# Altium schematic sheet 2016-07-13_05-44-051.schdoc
size 331 x 127 mm; SheetNumber: 1; SheetTotal: 1
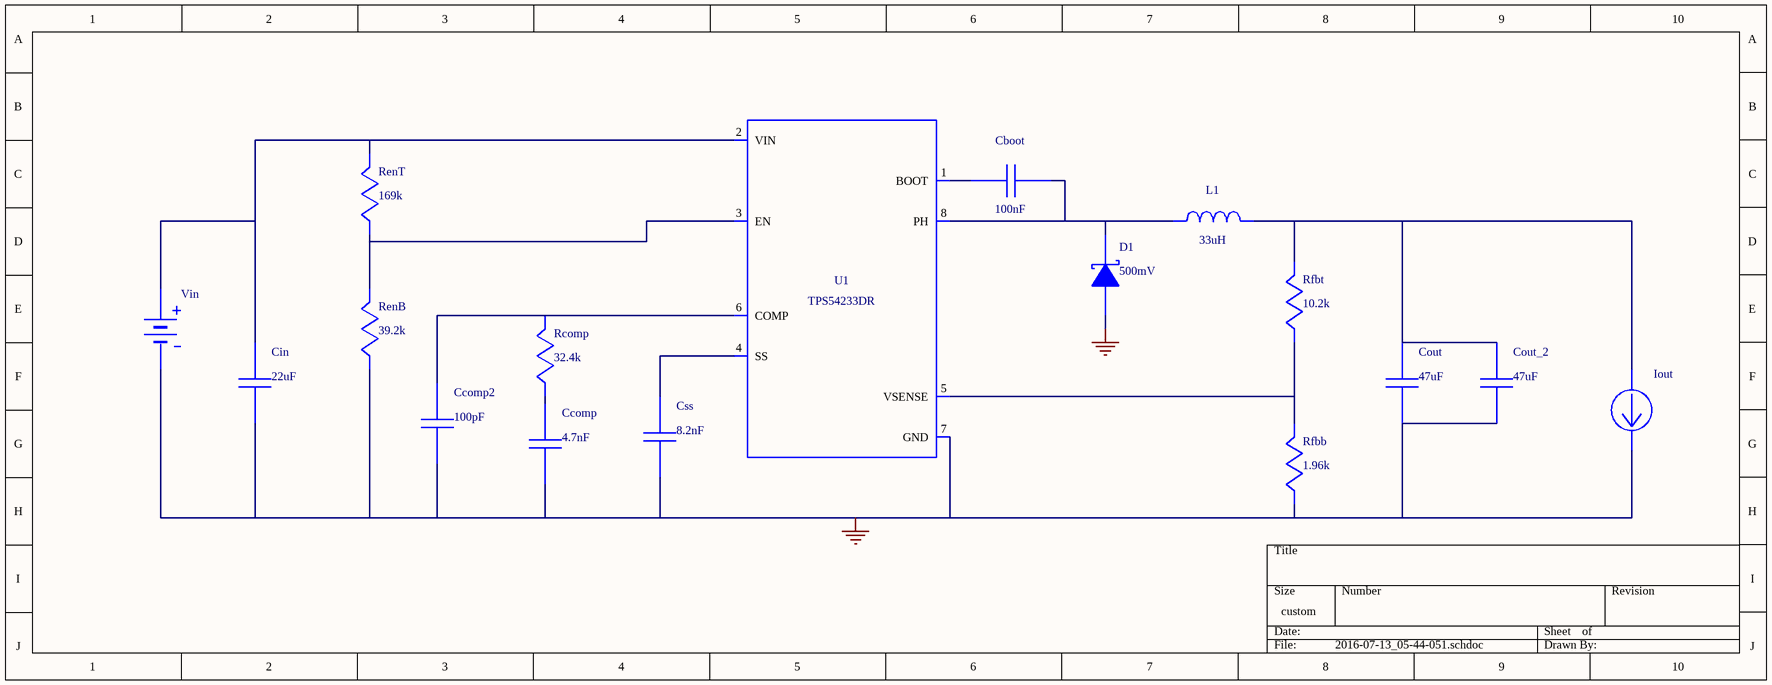
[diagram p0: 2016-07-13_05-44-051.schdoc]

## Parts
Cboot  value 100nF  (hidden comment: GRM155R61A104KA01D)
Ccomp  value 4.7nF  (hidden comment: CC0805KRX7R9BB472)
Ccomp2  value 100pF  (hidden comment: CC0805JRNPO9BN101)
Cin  value 22uF  (hidden comment: GRM32ER61E226KE15L)
Cout  value 47uF  (hidden comment: GRM31CR61A476KE15L)
Cout_2  value 47uF  (hidden comment: GRM31CR61A476KE15L)
Css  value 8.2nF  (hidden comment: GRM033R61A822KA01D)
D1  value 500mV  (hidden comment: B220-13-F)
Iout  WB_CURRENT_LOAD  (value not drawn)
L1  value 33uH  (hidden comment: SDR1105-330KL)
Rcomp  value 32.4k  (hidden comment: CRCW040232K4FKED)
RenB  value 39.2k  (hidden comment: CRCW040239K2FKED)
RenT  value 169k  (hidden comment: CRCW0402169KFKED)
Rfbb  value 1.96k  (hidden comment: CRCW04021K96FKED)
Rfbt  value 10.2k  (hidden comment: CRCW040210K2FKED)
U1  TPS54231DR  (value not drawn)
Vin  WB_BATTERY  (value not drawn)

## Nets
0: Ccomp.2 Ccomp2.2 Cin.2 Cout.2 Cout_2.2 Css.2 D1.2(A) Iout.2(-) RenB.2 Rfbb.2 U1.7(GND) Vin.2(-)
NetCboot_1: Cboot.1 U1.1(BOOT)
NetCboot_2: Cboot.2 D1.1(K) L1.2 U1.8(PH)
NetCcomp2_1: Ccomp2.1 Rcomp.1 U1.6(COMP)
NetCcomp_1: Ccomp.1 Rcomp.2
NetCin_1: Cin.1 RenT.1 U1.2(VIN) Vin.1(+)
NetCout_1: Cout.1 Cout_2.1 Iout.1(+) L1.1 Rfbt.1
NetCss_1: Css.1 U1.4(SS)
NetRenB_1: RenB.1 RenT.2 U1.3(EN)
NetRfbb_1: Rfbb.1 Rfbt.2 U1.5(VSENSE)

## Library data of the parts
Cboot = GRM155R61A104KA01D: GRM155R61A104KA0; Manufacturer Name: MuRata
Ccomp = CC0805KRX7R9BB472: CC0805KRX7R9BB47; Manufacturer Name: Yageo America
Ccomp2 = CC0805JRNPO9BN101: CC0805JRNPO9BN10; Manufacturer Name: Yageo America
Cin = GRM32ER61E226KE15L: GRM32ER61E226KE1; Manufacturer Name: MuRata
Cout Cout_2 = GRM31CR61A476KE15L: GRM31CR61A476KE1; Manufacturer Name: MuRata
Css = GRM033R61A822KA01D: GRM033R61A822KA0; Manufacturer Name: MuRata
D1 = B220-13-F: Manufacturer Name: Diodes Inc.
L1 = SDR1105-330KL: Manufacturer Name: Bourns
Rcomp = CRCW040232K4FKED: Manufacturer Name: Vishay-Dale
RenB = CRCW040239K2FKED: Manufacturer Name: Vishay-Dale
RenT = CRCW0402169KFKED: Manufacturer Name: Vishay-Dale
Rfbb = CRCW04021K96FKED: Manufacturer Name: Vishay-Dale
Rfbt = CRCW040210K2FKED: Manufacturer Name: Vishay-Dale
U1 = TPS54231DR: TPS54233DR; Manufacturer Name: Texas Instruments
